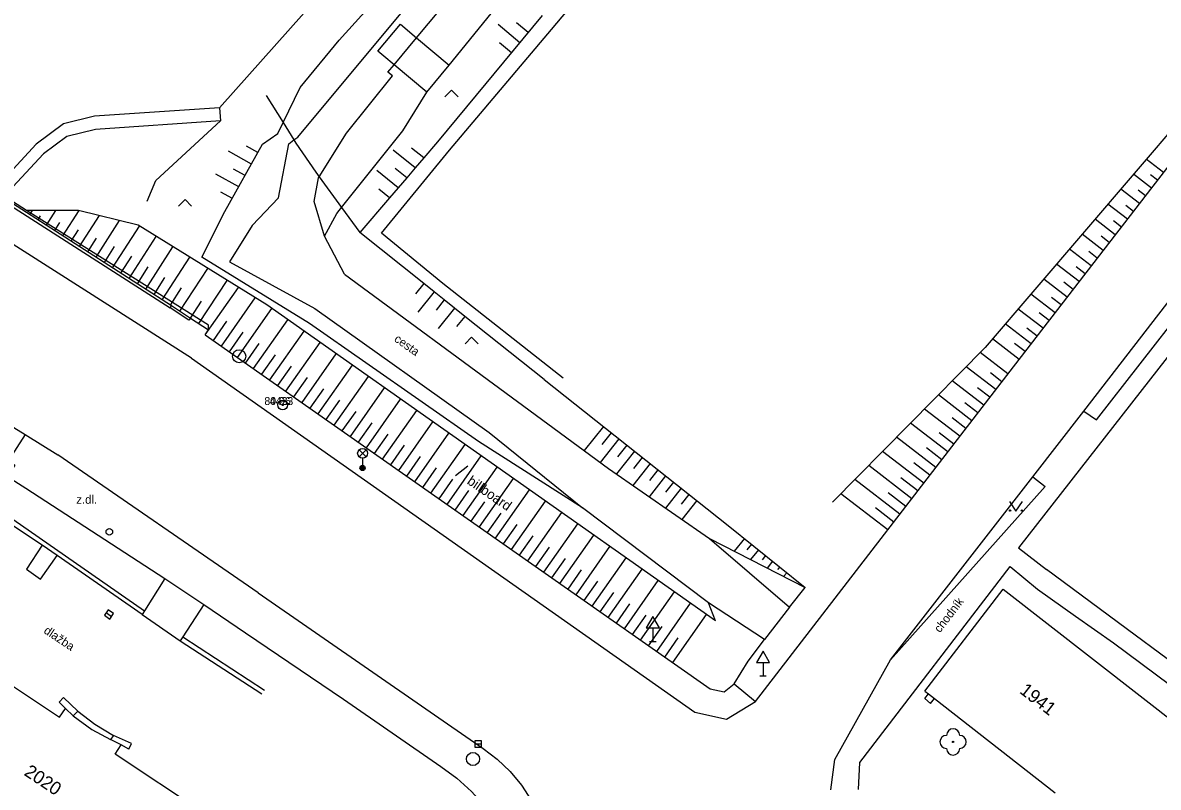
# Model space of a CAD drawing. Extents: x -538441 to -536770, y -1181008 to -1179809.
# Drawn here: x -537975.1 to -537888.6, y -1180382.1 to -1180323.8 of the extents above; entities that cross this region are included whole.
import ezdxf

# ---------------------------------------------------------------- set-up
doc = ezdxf.new("R2010")
doc.units = 0
for name, color, linetype in [('Vrstva 10', 7, 'Continuous'), ('Vrstva 11', 7, 'Continuous'), ('Vrstva 14', 7, 'Continuous'), ('Vrstva 15', 7, 'Continuous'), ('Vrstva 21', 7, 'Continuous'), ('Vrstva 22', 7, 'Continuous'), ('Vrstva 23', 7, 'Continuous'), ('Vrstva 27', 7, 'Continuous'), ('Vrstva 28', 7, 'Continuous'), ('Vrstva 33', 7, 'Continuous'), ('Vrstva 34', 7, 'Continuous'), ('Vrstva 36', 7, 'Continuous'), ('Vrstva 40', 7, 'Continuous'), ('Vrstva 41', 7, 'Continuous'), ('Vrstva 47', 7, 'Continuous'), ('Vrstva 5', 7, 'Continuous'), ('Vrstva 7', 7, 'Continuous'), ('Vrstva 8', 7, 'Continuous'), ('Vrstva 9', 7, 'Continuous')]:
    doc.layers.add(name, color=color, linetype=linetype)

msp = doc.modelspace()

# ---------------------------------------------------------------- linework, layer by layer
at = {"layer": 'Vrstva 10'}
for p, q in [((-537899.19, -1180349.5), (-537867.99, -1180309.109)), ((-537894.24, -1180353.438), (-537861.96, -1180311.539)), ((-537960.08, -1180330.32), (-537960.013, -1180331.32)), ((-537969.542, -1180331.969), (-537971.725, -1180332.508)), ((-537960.013, -1180331.32), (-537969.542, -1180331.969)), ((-537971.725, -1180332.508), (-537973.492, -1180333.844)), ((-537976.721, -1180337.311), (-537963.851, -1180345.57)), ((-537960.929, -1180346.879), (-537974.779, -1180338.141)), ((-537962.23, -1180349.391), (-537978.395, -1180339.106)), ((-537963.851, -1180345.57), (-537963.74, -1180345.398)), ((-537962.43, -1180346.5), (-537963.851, -1180345.57)), ((-537962.3, -1180346.344), (-537962.43, -1180346.5)), ((-537960.926, -1180347.25), (-537960.929, -1180346.879)), ((-537962.23, -1180349.391), (-537923.88, -1180376.367)), ((-537919.25, -1180375.563), (-537899.19, -1180349.5)), ((-537898.14, -1180358.453), (-537894.24, -1180353.438)), ((-537957.15, -1180367.281), (-537972.41, -1180356.761)), ((-537942.1, -1180358.336), (-537941.18, -1180357.602)), ((-537908.98, -1180372.398), (-537898.14, -1180358.453)), ((-537957.15, -1180367.281), (-537940.01, -1180379.15)), ((-537913.21, -1180379.969), (-537908.98, -1180372.398)), ((-537921.46, -1180376.898), (-537919.25, -1180375.563)), ((-537923.88, -1180376.367), (-537921.46, -1180376.898)), ((-537913.52, -1180382.297), (-537913.21, -1180379.969))]:
    msp.add_line(p, q, dxfattribs=at)
for points in [[(-537973.492, -1180333.844), (-537976.489, -1180337.062), (-537976.562, -1180337.141)], [(-537974.779, -1180338.141), (-537976.489, -1180337.062), (-537977.275, -1180336.566)], [(-537986.666, -1180347.976), (-537974.901, -1180355.226), (-537972.41, -1180356.761)], [(-537940.01, -1180379.15), (-537938.927, -1180379.96), (-537937.948, -1180380.893), (-537937.085, -1180381.934), (-537936.351, -1180383.07), (-537936.06, -1180383.62)]]:
    msp.add_lwpolyline(points, dxfattribs=at)
at = {"layer": 'Vrstva 11'}
for p, q in [((-537893.28, -1180354.109), (-537858.48, -1180309.328)), ((-537858.89, -1180312.141), (-537899.23, -1180363.844)), ((-537934.794, -1180324.356), (-537927.098, -1180315.015)), ((-537954.13, -1180332.56), (-537940.53, -1180316.23)), ((-537942.573, -1180333.565), (-537934.794, -1180324.356)), ((-537946.9, -1180327.9), (-537947.27, -1180327.62)), ((-537950.41, -1180332.27), (-537946.9, -1180327.9)), ((-537947.753, -1180339.875), (-537942.573, -1180333.565)), ((-537943.071, -1180343.703), (-537947.753, -1180339.875)), ((-537950.57, -1180343.01), (-537937.38, -1180352.71)), ((-537933.92, -1180350.924), (-537943.071, -1180343.703)), ((-537952.83, -1180345.63), (-537939.56, -1180355.06)), ((-537937.38, -1180352.71), (-537930.46, -1180357.805)), ((-537894.24, -1180353.438), (-537893.28, -1180354.109)), ((-537939.56, -1180355.06), (-537932.43, -1180360.812)), ((-537930.46, -1180357.805), (-537922.769, -1180363.146)), ((-537898.14, -1180358.453), (-537897.19, -1180359.188)), ((-537974.84, -1180359.31), (-537967.29, -1180364.22)), ((-537897.19, -1180359.188), (-537908.98, -1180372.398)), ((-537922.852, -1180368.034), (-537932.43, -1180360.812)), ((-537922.769, -1180363.146), (-537916.665, -1180368.365)), ((-537899.23, -1180363.844), (-537897.09, -1180365.5)), ((-537911.32, -1180380.211), (-537899.87, -1180365.281)), ((-537899.87, -1180365.281), (-537897.78, -1180367.008)), ((-537890.345, -1180370.51), (-537897.09, -1180365.5)), ((-537916.665, -1180368.365), (-537915.466, -1180366.885)), ((-537918.583, -1180370.834), (-537922.852, -1180368.034)), ((-537916.665, -1180368.365), (-537918.583, -1180370.834)), ((-537958.12, -1180370.33), (-537950.65, -1180375.37)), ((-537883.6, -1180375.52), (-537890.345, -1180370.51)), ((-537892, -1180371.09), (-537886.212, -1180375.407)), ((-537950.65, -1180375.37), (-537943.24, -1180380.5)), ((-537911.42, -1180382.258), (-537911.32, -1180380.211))]:
    msp.add_line(p, q, dxfattribs=at)
for points in [[(-537947.27, -1180327.62), (-537946.793, -1180327.048), (-537945.08, -1180324.991), (-537937.91, -1180316.38)], [(-537957.59, -1180339.29), (-537955.6, -1180337.18), (-537954.8, -1180333.06), (-537954.417, -1180332.774), (-537954.13, -1180332.56)], [(-537952.08, -1180340.1), (-537952.87, -1180337.47), (-537952.55, -1180335.65), (-537952.502, -1180335.574), (-537950.41, -1180332.27)], [(-537957.59, -1180339.29), (-537959.32, -1180342.05), (-537952.83, -1180345.63)], [(-537950.57, -1180343.01), (-537952.08, -1180340.1)], [(-537974.901, -1180355.226), (-537976.15, -1180357.2), (-537975.67, -1180357.56), (-537976.23, -1180358.41), (-537974.84, -1180359.31)], [(-537967.29, -1180364.22), (-537964.24, -1180366.2), (-537961.29, -1180368.18), (-537958.12, -1180370.33)], [(-537964.24, -1180366.2), (-537965.792, -1180368.64), (-537965.982, -1180368.939), (-537963.08, -1180370.94)], [(-537897.78, -1180367.008), (-537894.89, -1180369.049), (-537892, -1180371.09)], [(-537961.29, -1180368.18), (-537962.89, -1180370.646), (-537963.08, -1180370.94)], [(-537920.88, -1180374.203), (-537919.811, -1180372.477), (-537918.583, -1180370.834)], [(-537943.24, -1180380.5), (-537942.011, -1180381.391), (-537940.882, -1180382.407), (-537939.867, -1180383.536), (-537938.976, -1180384.765), (-537938.23, -1180386.06)]]:
    msp.add_lwpolyline(points, dxfattribs=at)
at = {"layer": 'Vrstva 14'}
for p, q in [((-537867.99, -1180309.109), (-537901.77, -1180348.594)), ((-537944.22, -1180312.498), (-537960.08, -1180330.32)), ((-537950.98, -1180325.17), (-537946.445, -1180320.122)), ((-537942.587, -1180327.083), (-537937.43, -1180320.71)), ((-537935.504, -1180323.301), (-537943.489, -1180332.929)), ((-537946.13, -1180332.08), (-537944.307, -1180329.133)), ((-537969.61, -1180330.961), (-537971.96, -1180331.539)), ((-537960.08, -1180330.32), (-537969.61, -1180330.961)), ((-537971.96, -1180331.539), (-537974.04, -1180333.102)), ((-537964.94, -1180335.86), (-537960.013, -1180331.32)), ((-537959.67, -1180338.24), (-537956.81, -1180333.09)), ((-537965.598, -1180337.44), (-537964.94, -1180335.86)), ((-537970.82, -1180338.141), (-537974.779, -1180338.141)), ((-537966.292, -1180339.266), (-537970.82, -1180338.141)), ((-537961.44, -1180341.71), (-537959.67, -1180338.24)), ((-537952.08, -1180340.1), (-537951.15, -1180338.37)), ((-537956.49, -1180345.344), (-537966.292, -1180339.266)), ((-537953.23, -1180346.76), (-537961.44, -1180341.71)), ((-537963.74, -1180345.398), (-537962.3, -1180346.344)), ((-537922.31, -1180369.406), (-537956.49, -1180345.344)), ((-537962.3, -1180346.344), (-537960.926, -1180347.25)), ((-537961.17, -1180347.617), (-537960.926, -1180347.25)), ((-537940.35, -1180355.74), (-537953.23, -1180346.76)), ((-537961.17, -1180347.617), (-537922.72, -1180374.594)), ((-537901.77, -1180348.594), (-537913.386, -1180360.364)), ((-537935.37, -1180351.03), (-537921.353, -1180362.142)), ((-537932.43, -1180360.812), (-537940.35, -1180355.74)), ((-537921.353, -1180362.142), (-537915.466, -1180366.885)), ((-537922.769, -1180363.146), (-537915.466, -1180366.885)), ((-537922.31, -1180369.406), (-537922.852, -1180368.034)), ((-537921.66, -1180374.813), (-537920.88, -1180374.203)), ((-537920.88, -1180374.203), (-537919.25, -1180375.563)), ((-537922.72, -1180374.594), (-537921.66, -1180374.813))]:
    msp.add_line(p, q, dxfattribs=at)
for points in [[(-537956.81, -1180333.09), (-537955.64, -1180332.28), (-537955.243, -1180331.455), (-537953.95, -1180328.77), (-537950.98, -1180325.17)], [(-537951.15, -1180338.37), (-537950.792, -1180337.921), (-537946.13, -1180332.08)], [(-537974.04, -1180333.102), (-537977.275, -1180336.566), (-537977.345, -1180336.641)], [(-537943.489, -1180332.929), (-537944.528, -1180334.141), (-537945.18, -1180334.901), (-537945.83, -1180335.66), (-537946.481, -1180336.42), (-537947.132, -1180337.18), (-537949.402, -1180339.829)]]:
    msp.add_lwpolyline(points, dxfattribs=at)
at = {"layer": 'Vrstva 15'}
for p, q in [((-537937.216, -1180325.365), (-537938.868, -1180323.97)), ((-537936.577, -1180324.595), (-537937.459, -1180323.851)), ((-537937.854, -1180326.135), (-537938.749, -1180325.379)), ((-537957.654, -1180334.61), (-537959.402, -1180333.639)), ((-537957.168, -1180333.736), (-537958.042, -1180333.25)), ((-537945.18, -1180334.901), (-537946.864, -1180333.553)), ((-537944.528, -1180334.141), (-537945.458, -1180333.397)), ((-537888.186, -1180335.255), (-537889.494, -1180334.245)), ((-537958.624, -1180336.358), (-537960.373, -1180335.387)), ((-537958.139, -1180335.484), (-537959.013, -1180334.999)), ((-537946.481, -1180336.42), (-537948.113, -1180335.114)), ((-537945.83, -1180335.66), (-537946.708, -1180334.958)), ((-537889.103, -1180336.442), (-537890.47, -1180335.386)), ((-537888.645, -1180335.848), (-537889.18, -1180335.435)), ((-537959.11, -1180337.232), (-537959.984, -1180336.747)), ((-537947.132, -1180337.18), (-537947.957, -1180336.52)), ((-537890.02, -1180337.629), (-537891.447, -1180336.527)), ((-537889.562, -1180337.036), (-537890.12, -1180336.604)), ((-537890.937, -1180338.816), (-537892.423, -1180337.668)), ((-537890.479, -1180338.223), (-537891.061, -1180337.773)), ((-537974.533, -1180338.45), (-537974.334, -1180338.141)), ((-537973.902, -1180338.856), (-537973.718, -1180338.57)), ((-537973.271, -1180339.262), (-537972.549, -1180338.141)), ((-537972.01, -1180340.074), (-537970.773, -1180338.153)), ((-537970.749, -1180340.886), (-537969.235, -1180338.535)), ((-537891.854, -1180340.003), (-537893.4, -1180338.81)), ((-537972.641, -1180339.668), (-537972.248, -1180339.057)), ((-537971.38, -1180340.48), (-537970.83, -1180339.625)), ((-537969.488, -1180341.698), (-537967.697, -1180338.917)), ((-537968.226, -1180342.51), (-537966.182, -1180339.334)), ((-537891.396, -1180339.41), (-537892.002, -1180338.942)), ((-537970.118, -1180341.292), (-537969.457, -1180340.265)), ((-537966.965, -1180343.322), (-537964.907, -1180340.125)), ((-537892.771, -1180341.19), (-537894.376, -1180339.951)), ((-537892.313, -1180340.597), (-537892.943, -1180340.11)), ((-537968.857, -1180342.104), (-537968.086, -1180340.905)), ((-537965.704, -1180344.134), (-537963.632, -1180340.915)), ((-537893.688, -1180342.377), (-537895.352, -1180341.092)), ((-537893.23, -1180341.784), (-537893.883, -1180341.279)), ((-537967.596, -1180342.916), (-537966.775, -1180341.641)), ((-537964.443, -1180344.946), (-537962.357, -1180341.706)), ((-537894.605, -1180343.565), (-537896.329, -1180342.234)), ((-537966.335, -1180343.728), (-537965.509, -1180342.445)), ((-537963.113, -1180345.81), (-537960.979, -1180342.561)), ((-537894.147, -1180342.971), (-537894.824, -1180342.448)), ((-537965.073, -1180344.54), (-537964.242, -1180343.248)), ((-537963.812, -1180345.352), (-537962.975, -1180344.051)), ((-537961.675, -1180346.757), (-537959.51, -1180343.472)), ((-537961.17, -1180347.617), (-537958.64, -1180344.011)), ((-537944.528, -1180343.72), (-537945.149, -1180344.497)), ((-537895.522, -1180344.752), (-537897.305, -1180343.375)), ((-537895.064, -1180344.158), (-537895.765, -1180343.616)), ((-537959.942, -1180348.479), (-537957.363, -1180344.803)), ((-537943.746, -1180344.344), (-537944.992, -1180345.902)), ((-537896.439, -1180345.939), (-537898.281, -1180344.516)), ((-537895.981, -1180345.345), (-537896.705, -1180344.785)), ((-537962.301, -1180346.344), (-537961.452, -1180345.055)), ((-537958.714, -1180349.34), (-537956.102, -1180345.617)), ((-537942.965, -1180344.968), (-537943.586, -1180345.745)), ((-537942.184, -1180345.592), (-537943.429, -1180347.151)), ((-537897.356, -1180347.126), (-537899.258, -1180345.657)), ((-537960.556, -1180348.048), (-537959.534, -1180346.591)), ((-537957.486, -1180350.202), (-537954.875, -1180346.481)), ((-537941.402, -1180346.216), (-537942.024, -1180346.994)), ((-537896.898, -1180346.532), (-537897.646, -1180345.954)), ((-537959.328, -1180348.909), (-537958.287, -1180347.425)), ((-537956.258, -1180351.063), (-537953.649, -1180347.344)), ((-537898.273, -1180348.313), (-537900.234, -1180346.798)), ((-537897.815, -1180347.719), (-537898.587, -1180347.123)), ((-537958.1, -1180349.771), (-537957.056, -1180348.282)), ((-537955.03, -1180351.925), (-537952.423, -1180348.207)), ((-537899.19, -1180349.5), (-537901.21, -1180347.94)), ((-537898.732, -1180348.906), (-537899.528, -1180348.291)), ((-537956.872, -1180350.632), (-537955.828, -1180349.144)), ((-537953.802, -1180352.786), (-537951.196, -1180349.071)), ((-537900.037, -1180350.601), (-537902.148, -1180348.977)), ((-537955.644, -1180351.494), (-537954.601, -1180350.007)), ((-537952.575, -1180353.648), (-537949.969, -1180349.934)), ((-537900.952, -1180351.789), (-537903.209, -1180350.052)), ((-537954.416, -1180352.355), (-537953.374, -1180350.869)), ((-537951.347, -1180354.509), (-537948.743, -1180350.798)), ((-537900.495, -1180351.195), (-537901.368, -1180350.523)), ((-537953.189, -1180353.217), (-537952.146, -1180351.731)), ((-537950.119, -1180355.371), (-537947.516, -1180351.661)), ((-537901.867, -1180352.978), (-537904.271, -1180351.128)), ((-537901.41, -1180352.384), (-537902.342, -1180351.666)), ((-537951.961, -1180354.078), (-537950.919, -1180352.593)), ((-537948.891, -1180356.232), (-537946.29, -1180352.525)), ((-537902.782, -1180354.167), (-537905.332, -1180352.204)), ((-537950.733, -1180354.94), (-537949.691, -1180353.456)), ((-537947.663, -1180357.094), (-537945.063, -1180353.388)), ((-537903.697, -1180355.355), (-537906.394, -1180353.279)), ((-537902.324, -1180353.572), (-537903.315, -1180352.81)), ((-537949.505, -1180355.801), (-537948.464, -1180354.318)), ((-537946.435, -1180357.955), (-537943.836, -1180354.252)), ((-537904.612, -1180356.544), (-537907.456, -1180354.355)), ((-537903.239, -1180354.761), (-537904.289, -1180353.953)), ((-537948.277, -1180356.663), (-537947.237, -1180355.18)), ((-537945.207, -1180358.817), (-537942.61, -1180355.115)), ((-537930.85, -1180354.613), (-537932.304, -1180356.447)), ((-537930.257, -1180355.083), (-537930.976, -1180355.99)), ((-537904.154, -1180355.95), (-537905.263, -1180355.097)), ((-537947.049, -1180357.525), (-537946.009, -1180356.043)), ((-537943.979, -1180359.678), (-537941.383, -1180355.979)), ((-537929.665, -1180355.553), (-537931.085, -1180357.345)), ((-537929.072, -1180356.023), (-537929.774, -1180356.908)), ((-537905.527, -1180357.733), (-537908.518, -1180355.431)), ((-537945.821, -1180358.386), (-537944.782, -1180356.905)), ((-537942.751, -1180360.54), (-537940.157, -1180356.842)), ((-537928.479, -1180356.493), (-537929.854, -1180358.226)), ((-537927.887, -1180356.962), (-537928.559, -1180357.81)), ((-537906.441, -1180358.921), (-537909.579, -1180356.507)), ((-537905.069, -1180357.138), (-537906.236, -1180356.24)), ((-537944.593, -1180359.248), (-537943.555, -1180357.767)), ((-537941.523, -1180361.401), (-537938.93, -1180357.706)), ((-537927.294, -1180357.432), (-537928.609, -1180359.091)), ((-537926.701, -1180357.902), (-537927.344, -1180358.713)), ((-537907.356, -1180360.11), (-537910.641, -1180357.582)), ((-537905.984, -1180358.327), (-537907.21, -1180357.384)), ((-537943.365, -1180360.109), (-537942.327, -1180358.63)), ((-537940.295, -1180362.263), (-537937.703, -1180358.569)), ((-537926.108, -1180358.372), (-537927.364, -1180359.955)), ((-537908.271, -1180361.299), (-537911.703, -1180358.658)), ((-537906.899, -1180359.516), (-537908.183, -1180358.527)), ((-537942.137, -1180360.971), (-537941.1, -1180359.492)), ((-537939.067, -1180363.124), (-537936.477, -1180359.433)), ((-537925.516, -1180358.842), (-537926.128, -1180359.615)), ((-537924.923, -1180359.312), (-537926.119, -1180360.82)), ((-537940.909, -1180361.832), (-537939.872, -1180360.354)), ((-537937.84, -1180363.986), (-537935.251, -1180360.296)), ((-537924.33, -1180359.782), (-537924.913, -1180360.517)), ((-537923.738, -1180360.251), (-537924.874, -1180361.684)), ((-537909.186, -1180362.488), (-537912.764, -1180359.734)), ((-537907.814, -1180360.704), (-537909.157, -1180359.671)), ((-537939.681, -1180362.694), (-537938.645, -1180361.216)), ((-537936.612, -1180364.847), (-537934.024, -1180361.159)), ((-537908.729, -1180361.893), (-537910.13, -1180360.814)), ((-537938.454, -1180363.555), (-537937.418, -1180362.079)), ((-537935.384, -1180365.709), (-537932.798, -1180362.023)), ((-537937.226, -1180364.417), (-537936.19, -1180362.941)), ((-537934.156, -1180366.57), (-537931.571, -1180362.886)), ((-537935.998, -1180365.278), (-537934.963, -1180363.803)), ((-537932.928, -1180367.432), (-537930.345, -1180363.75)), ((-537920.112, -1180363.142), (-537920.89, -1180364.108)), ((-537919.573, -1180363.576), (-537919.917, -1180364.003)), ((-537934.77, -1180366.14), (-537933.736, -1180364.666)), ((-537931.7, -1180368.294), (-537929.118, -1180364.613)), ((-537919.035, -1180364.01), (-537919.633, -1180364.752)), ((-537918.496, -1180364.444), (-537918.75, -1180364.759)), ((-537933.542, -1180367.001), (-537932.508, -1180365.528)), ((-537930.472, -1180369.155), (-537927.891, -1180365.477)), ((-537917.958, -1180364.878), (-537918.375, -1180365.396)), ((-537917.419, -1180365.311), (-537917.583, -1180365.514)), ((-537932.314, -1180367.863), (-537931.281, -1180366.39)), ((-537929.244, -1180370.017), (-537926.665, -1180366.34)), ((-537916.881, -1180365.745), (-537917.118, -1180366.039)), ((-537931.086, -1180368.724), (-537930.053, -1180367.253)), ((-537928.016, -1180370.878), (-537925.438, -1180367.204)), ((-537929.858, -1180369.586), (-537928.826, -1180368.115)), ((-537926.788, -1180371.74), (-537924.212, -1180368.067)), ((-537928.63, -1180370.447), (-537927.599, -1180368.977)), ((-537925.56, -1180372.601), (-537922.985, -1180368.931)), ((-537927.402, -1180371.309), (-537926.371, -1180369.84)), ((-537926.174, -1180372.17), (-537925.144, -1180370.702))]:
    msp.add_line(p, q, dxfattribs=at)
at = {"layer": 'Vrstva 21'}
for radius in [0.375, 0.05]:
    msp.add_circle((-537955.28, -1180352.97), radius, dxfattribs=at)
at = {"layer": 'Vrstva 22'}
msp.add_circle((-537904.21, -1180378.641), 0.05, dxfattribs=at)
for centre, start, end in [((-537904.21, -1180378.141), 0, 180), ((-537904.71, -1180378.641), 90, 270), ((-537903.71, -1180378.641), 270, 90), ((-537904.21, -1180379.141), 180, 0)]:
    msp.add_arc(centre, 0.5, start, end, dxfattribs=at)
at = {"layer": 'Vrstva 27'}
for p, q in [((-537968.715, -1180368.787), (-537968.305, -1180369.073)), ((-537940.63, -1180378.797), (-537940.13, -1180378.797))]:
    msp.add_line(p, q, dxfattribs=at)
for points in [[(-537968.858, -1180368.992), (-537968.448, -1180369.278), (-537968.162, -1180368.868), (-537968.572, -1180368.582)], [(-537940.63, -1180379.047), (-537940.13, -1180379.047), (-537940.13, -1180378.547), (-537940.63, -1180378.547)]]:
    msp.add_lwpolyline(points, close=True, dxfattribs=at)
for centre in [(-537958.59, -1180349.258), (-537940.78, -1180379.94)]:
    msp.add_circle(centre, 0.5, dxfattribs=at)
at = {"layer": 'Vrstva 28'}
msp.add_circle((-537968.48, -1180362.64), 0.25, dxfattribs=at)
at = {"layer": 'Vrstva 33'}
for p, q in [((-537949.455, -1180356.913), (-537948.925, -1180356.383)), ((-537949.455, -1180356.383), (-537948.925, -1180356.913)), ((-537949.19, -1180357.023), (-537949.19, -1180357.773))]:
    msp.add_line(p, q, dxfattribs=at)
for centre, radius in [((-537949.19, -1180356.648), 0.375), ((-537949.19, -1180357.773), 0.2), ((-537949.19, -1180357.773), 0.145), ((-537949.19, -1180357.773), 0.0876)]:
    msp.add_circle(centre, radius, dxfattribs=at)
at = {"layer": 'Vrstva 34'}
for p, q in [((-537927.08, -1180369.959), (-537927.08, -1180370.977)), ((-537927.33, -1180370.977), (-537926.83, -1180370.977)), ((-537918.69, -1180372.591), (-537918.69, -1180373.609)), ((-537918.94, -1180373.609), (-537918.44, -1180373.609))]:
    msp.add_line(p, q, dxfattribs=at)
for points in [[(-537927.58, -1180369.959), (-537926.58, -1180369.959), (-537927.08, -1180369.093)], [(-537919.19, -1180372.591), (-537918.19, -1180372.591), (-537918.69, -1180371.725)]]:
    msp.add_lwpolyline(points, close=True, dxfattribs=at)
at = {"layer": 'Vrstva 36'}
for points in [[(-537942.915, -1180329.486), (-537942.415, -1180328.986), (-537941.915, -1180329.486)], [(-537963.21, -1180337.812), (-537962.71, -1180337.312), (-537962.21, -1180337.812)], [(-537941.383, -1180348.307), (-537940.883, -1180347.807), (-537940.383, -1180348.307)], [(-537899.922, -1180360.32), (-537899.422, -1180361.07), (-537898.922, -1180360.32)]]:
    msp.add_lwpolyline(points, dxfattribs=at)
for centre in [(-537899.872, -1180361.02), (-537898.973, -1180361.02)]:
    msp.add_circle(centre, 0.05, dxfattribs=at)
at = {"layer": 'Vrstva 5'}
for p, q in [((-537948.03, -1180326.01), (-537946.31, -1180323.96)), ((-537947.57, -1180326.396), (-537948.03, -1180326.01)), ((-537944.307, -1180329.133), (-537942.587, -1180327.083)), ((-537906.36, -1180374.773), (-537900.4, -1180367)), ((-537900.4, -1180367), (-537861.61, -1180397.25)), ((-537979.3, -1180372.07), (-537972.27, -1180376.76)), ((-537906.36, -1180374.773), (-537906.091, -1180374.983)), ((-537906.36, -1180375.328), (-537906.091, -1180374.983)), ((-537906.091, -1180374.983), (-537905.635, -1180375.338)), ((-537972.31, -1180375.61), (-537971.97, -1180375.26)), ((-537972.31, -1180375.61), (-537971.818, -1180376.083)), ((-537972.27, -1180376.76), (-537971.818, -1180376.083)), ((-537971.97, -1180375.26), (-537970.89, -1180376.3)), ((-537971.818, -1180376.083), (-537971.228, -1180376.651)), ((-537905.92, -1180375.703), (-537906.36, -1180375.328)), ((-537905.92, -1180375.703), (-537905.635, -1180375.338)), ((-537905.635, -1180375.338), (-537896.443, -1180382.507)), ((-537970.89, -1180376.3), (-537971.228, -1180376.651)), ((-537971.228, -1180376.651), (-537969.8, -1180377.69)), ((-537970.89, -1180376.3), (-537969.58, -1180377.29)), ((-537969.8, -1180377.69), (-537968.38, -1180378.46)), ((-537969.58, -1180377.29), (-537968.15, -1180378.16)), ((-537968.15, -1180378.16), (-537968.38, -1180378.46)), ((-537967.588, -1180378.872), (-537968.38, -1180378.46)), ((-537966.78, -1180378.76), (-537968.15, -1180378.16)), ((-537968.046, -1180379.563), (-537967.588, -1180378.872)), ((-537966.991, -1180379.183), (-537967.588, -1180378.872)), ((-537966.991, -1180379.183), (-537966.78, -1180378.76)), ((-537960.98, -1180384.25), (-537968.046, -1180379.563))]:
    msp.add_line(p, q, dxfattribs=at)
for points in [[(-537946.31, -1180323.96), (-537945.08, -1180324.991), (-537942.587, -1180327.083)], [(-537944.307, -1180329.133), (-537946.793, -1180327.048), (-537947.57, -1180326.396)]]:
    msp.add_lwpolyline(points, dxfattribs=at)
at = {"layer": 'Vrstva 7'}
for p, q in [((-537975.832, -1180361.664), (-537965.792, -1180368.64)), ((-537972.442, -1180364.444), (-537973.6, -1180363.66)), ((-537965.982, -1180368.939), (-537972.442, -1180364.444)), ((-537962.89, -1180370.646), (-537956.662, -1180374.685)), ((-537963.08, -1180370.94), (-537956.852, -1180374.979))]:
    msp.add_line(p, q, dxfattribs=at)
for points in [[(-537956.54, -1180329.38), (-537955.243, -1180331.455), (-537954.417, -1180332.774), (-537954.27, -1180333.01)], [(-537952.76, -1180335.22), (-537952.502, -1180335.574), (-537950.792, -1180337.921), (-537949.402, -1180339.829)], [(-537935.37, -1180351.03), (-537941.402, -1180346.216), (-537942.184, -1180345.592), (-537942.965, -1180344.968), (-537943.746, -1180344.344), (-537944.528, -1180343.72), (-537949.402, -1180339.829)], [(-537973.6, -1180363.66), (-537975.939, -1180362.105), (-537976.15, -1180361.96)], [(-537973.6, -1180363.66), (-537974.78, -1180365.47), (-537973.71, -1180366.23), (-537972.442, -1180364.444)]]:
    msp.add_lwpolyline(points, dxfattribs=at)
at = {"layer": 'Vrstva 8'}
msp.add_line((-537954.27, -1180333.01), (-537952.76, -1180335.22), dxfattribs=at)
at = {"layer": 'Vrstva 9'}
msp.add_line((-537982.1, -1180333.578), (-537963.74, -1180345.398), dxfattribs=at)

# ---------------------------------------------------------------- texts
at = {"layer": 'Vrstva 22'}
msp.add_text('80.96', height=0.6, dxfattribs=at).set_placement((-537956.669, -1180352.97))
at = {"layer": 'Vrstva 23'}
msp.add_text('4423', height=0.6, dxfattribs=at).set_placement((-537956.258, -1180352.97))
at = {"layer": 'Vrstva 40'}
for s, rotation, p in [('cesta', 324.60143, (-537946.841, -1180348.065)), ('chodník', 52.53869, (-537905.213, -1180370.367)), ('dlažba', 326.29113, (-537973.531, -1180370.301))]:
    msp.add_text(s, height=0.65, rotation=rotation, dxfattribs=at).set_placement(p)
msp.add_text('z.dl.', height=0.65, dxfattribs=at).set_placement((-537970.998, -1180360.495))
at = {"layer": 'Vrstva 41'}
msp.add_text('billboard', height=0.75, rotation=325.43689, dxfattribs=at).set_placement((-537941.29, -1180358.922))
at = {"layer": 'Vrstva 47'}
for s, rotation, p in [('1941', 322.07983, (-537899.214, -1180374.863)), ('2020', 326.42594, (-537975.04, -1180381.127))]:
    msp.add_text(s, height=1, rotation=rotation, dxfattribs=at).set_placement(p)

doc.saveas('drawing.dxf')
